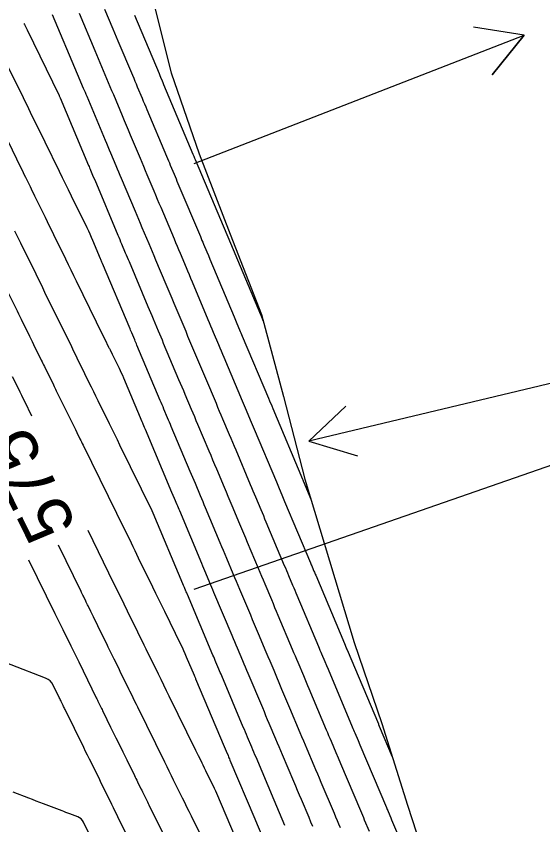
# Model space of a CAD drawing. Extents: x 954385 to 988206, y 1868364 to 1924553.
# Drawn here: x 957986.2 to 958048.1, y 1919141.2 to 1919236.3 of the extents above; entities that cross this region are included whole.
import ezdxf

# ---------------------------------------------------------------- set-up
doc = ezdxf.new("R2010")
doc.units = 0
for name, color, linetype in [('24', 7, 'Continuous'), ('26', 7, 'Continuous'), ('5', 7, 'Continuous'), ('6', 7, 'Continuous'), ('7', 7, 'Continuous')]:
    doc.layers.add(name, color=color, linetype=linetype)

msp = doc.modelspace()

# ---------------------------------------------------------------- linework, layer by layer
at = {"layer": '24'}
msp.add_lwpolyline([(958002.021, 1919239.295), (958004.432, 1919229.588), (958007.744, 1919220.082), (958011.352, 1919210.643), (958015.035, 1919201.221), (958017.626, 1919191.554), (958020.15, 1919181.871), (958023.018, 1919172.266), (958025.931, 1919162.671), (958029.184, 1919153.153), (958032.173, 1919143.575), (958035.293, 1919134.026), (958036.808, 1919124.117), (958038.226, 1919114.187), (958040.213, 1919104.384), (958041.632, 1919094.454), (958042.392, 1919084.376), (958043.229, 1919074.315), (958044.113, 1919064.265)], dxfattribs=at)
at = {"layer": '26'}
for points in [[(958007.131, 1919218.928), (958045.875, 1919234.038), (958042.124, 1919229.355), (958045.875, 1919234.038), (958039.944, 1919234.945)], [(958157.131, 1919218.928), (958020.586, 1919186.323), (958024.943, 1919190.448), (958020.586, 1919186.323), (958026.337, 1919184.612)], [(958007.131, 1919168.928), (958086.983, 1919196.694), (958083.061, 1919192.154), (958086.983, 1919196.694), (958081.09, 1919197.821)]]:
    msp.add_lwpolyline(points, dxfattribs=at)
at = {"layer": '6'}
for points in [[(958000.126, 1919236.367), (958003.015, 1919229.499), (958003.103, 1919229.29), (958003.191, 1919229.08), (958003.368, 1919228.661), (958003.456, 1919228.451), (958003.544, 1919228.242), (958006.998, 1919220.027), (958007.085, 1919219.821), (958007.193, 1919219.564), (958007.258, 1919219.409), (958010.962, 1919210.61), (958011.088, 1919210.312), (958014.918, 1919201.21), (958014.953, 1919201.127), (958015.248, 1919200.428)], [(958024.32, 1919140.894), (958024.142, 1919141.313), (958023.965, 1919141.733), (958023.788, 1919142.152), (958023.61, 1919142.572), (958022.061, 1919146.233), (958021.855, 1919146.719), (958021.65, 1919147.205), (958021.444, 1919147.691), (958021.238, 1919148.177), (958020.416, 1919150.121), (958020.21, 1919150.607), (958020.005, 1919151.093), (958019.8, 1919151.579), (958019.594, 1919152.066), (958018.375, 1919154.959), (958018.143, 1919155.509), (958017.911, 1919156.058), (958017.68, 1919156.608), (958017.448, 1919157.158), (958016.515, 1919159.372), (958016.286, 1919159.914), (958016.058, 1919160.456), (958015.83, 1919160.997), (958015.602, 1919161.539), (958014.689, 1919163.706), (958014.461, 1919164.247), (958014.233, 1919164.789), (958014.005, 1919165.331), (958013.777, 1919165.872), (958012.498, 1919168.907), (958012.306, 1919169.363), (958012.114, 1919169.819), (958011.922, 1919170.275), (958011.73, 1919170.731), (958010.964, 1919172.555), (958010.773, 1919173.011), (958010.581, 1919173.467), (958010.39, 1919173.923), (958010.198, 1919174.379), (958008.482, 1919178.47), (958008.331, 1919178.828), (958008.181, 1919179.186), (958008.03, 1919179.543), (958007.88, 1919179.901), (958007.276, 1919181.332), (958007.126, 1919181.69), (958006.975, 1919182.048), (958006.824, 1919182.406), (958006.673, 1919182.763), (958004.452, 1919188.036), (958004.344, 1919188.292), (958004.236, 1919188.549), (958004.127, 1919188.805), (958004.019, 1919189.062), (958003.587, 1919190.088), (958003.479, 1919190.344), (958003.371, 1919190.601), (958003.263, 1919190.857), (958003.154, 1919191.114), (958000.422, 1919197.591), (958000.355, 1919197.751), (958000.287, 1919197.911), (958000.22, 1919198.071), (958000.152, 1919198.232), (957999.815, 1919199.033), (957999.68, 1919199.353), (957999.613, 1919199.513), (957996.385, 1919207.184), (957996.308, 1919207.368), (957996.191, 1919207.645), (957996.152, 1919207.738), (957995.245, 1919209.894), (957995.085, 1919210.267), (957994.919, 1919210.638), (957994.749, 1919211.007), (957994.572, 1919211.373), (957992.737, 1919215.12), (957992.385, 1919215.838), (957992.033, 1919216.556), (957991.681, 1919217.275), (957991.329, 1919217.993), (957989.645, 1919221.432), (957989.431, 1919221.867), (957989.217, 1919222.303), (957989.004, 1919222.739), (957988.79, 1919223.175), (957987.936, 1919224.918), (957987.723, 1919225.354), (957987.509, 1919225.79), (957987.296, 1919226.226), (957987.082, 1919226.662), (957984.684, 1919231.558)], [(958008.14, 1919139.572), (958006.808, 1919142.274), (958006.547, 1919142.802), (958006.287, 1919143.329), (958006.027, 1919143.856), (958005.767, 1919144.384), (958004.727, 1919146.493), (958004.467, 1919147.02), (958004.207, 1919147.548), (958003.948, 1919148.076), (958003.688, 1919148.603), (958000.521, 1919155.056), (958000.352, 1919155.401), (958000.183, 1919155.745), (957999.76, 1919156.607), (957999.591, 1919156.951), (957999.507, 1919157.124), (957998.448, 1919159.28), (957998.273, 1919159.638), (957998.097, 1919159.995), (957997.922, 1919160.352), (957997.746, 1919160.71), (957997.044, 1919162.139), (957996.869, 1919162.496), (957996.693, 1919162.853), (957996.518, 1919163.211), (957996.343, 1919163.568), (957995.297, 1919165.702), (957995.221, 1919165.857), (957995.146, 1919166.012), (957995.07, 1919166.167), (957994.994, 1919166.322), (957994.678, 1919166.97), (957994.609, 1919167.111), (957994.54, 1919167.253), (957994.471, 1919167.394), (957994.401, 1919167.535), (957994.125, 1919168.1), (957994.056, 1919168.241), (957993.987, 1919168.383), (957993.918, 1919168.524), (957993.849, 1919168.665), (957991.192, 1919174.099)]]:
    msp.add_lwpolyline(points, dxfattribs=at)
at = {"layer": '7'}
for points in [[(957993.622, 1919236.596), (957995.457, 1919232.234), (957996.054, 1919230.814), (957996.85, 1919228.922), (957997.049, 1919228.449), (957997.248, 1919227.976), (957997.447, 1919227.502), (957997.646, 1919227.029), (957998.679, 1919224.577), (957998.917, 1919224.01), (957999.155, 1919223.444), (957999.393, 1919222.878), (957999.632, 1919222.311), (958000.783, 1919219.572), (958000.986, 1919219.091), (958001.188, 1919218.611), (958001.39, 1919218.13), (958001.592, 1919217.649), (958002.401, 1919215.727), (958002.603, 1919215.246), (958002.805, 1919214.766), (958003.008, 1919214.285), (958003.21, 1919213.804), (958004.776, 1919210.085), (958004.952, 1919209.666), (958005.128, 1919209.247), (958005.305, 1919208.828), (958005.481, 1919208.409), (958006.186, 1919206.732), (958006.363, 1919206.313), (958006.539, 1919205.894), (958006.715, 1919205.475), (958006.892, 1919205.056), (958008.758, 1919200.622), (958008.913, 1919200.252), (958009.069, 1919199.882), (958009.225, 1919199.512), (958009.381, 1919199.143), (958010.005, 1919197.664), (958010.161, 1919197.294), (958010.316, 1919196.925), (958010.472, 1919196.555), (958010.628, 1919196.185), (958012.78, 1919191.079), (958012.898, 1919190.799), (958013.016, 1919190.519), (958013.134, 1919190.24), (958013.252, 1919189.96), (958013.723, 1919188.841), (958013.841, 1919188.561), (958013.959, 1919188.281), (958014.077, 1919188.002), (958014.195, 1919187.722), (958016.802, 1919181.536), (958016.882, 1919181.346), (958016.962, 1919181.156), (958017.042, 1919180.965), (958017.122, 1919180.775), (958017.442, 1919180.014), (958017.522, 1919179.823), (958017.602, 1919179.633), (958017.682, 1919179.442), (958017.762, 1919179.252), (958020.793, 1919172.035), (958020.844, 1919171.912), (958020.896, 1919171.79), (958020.947, 1919171.667), (958020.999, 1919171.545), (958021.205, 1919171.056), (958021.257, 1919170.933), (958021.308, 1919170.811), (958021.36, 1919170.688), (958021.411, 1919170.566), (958024.788, 1919162.548), (958024.865, 1919162.365), (958025.044, 1919161.94), (958025.095, 1919161.818), (958028.768, 1919153.106), (958028.795, 1919153.043), (958028.875, 1919152.853), (958030.408, 1919149.229)], [(957996.626, 1919237.071), (957997.6, 1919234.755), (957998.184, 1919233.366), (957999.893, 1919229.304), (958000.034, 1919228.968), (958000.176, 1919228.633), (958000.317, 1919228.297), (958000.458, 1919227.961), (958001.023, 1919226.619), (958001.164, 1919226.283), (958001.305, 1919225.948), (958001.447, 1919225.612), (958001.588, 1919225.276), (958003.891, 1919219.8), (958004.003, 1919219.534), (958004.115, 1919219.268), (958004.227, 1919219.002), (958004.338, 1919218.735), (958004.786, 1919217.671), (958004.898, 1919217.405), (958005.01, 1919217.139), (958005.122, 1919216.873), (958005.234, 1919216.607), (958007.869, 1919210.347), (958007.962, 1919210.125), (958008.056, 1919209.903), (958008.149, 1919209.681), (958008.243, 1919209.46), (958008.616, 1919208.572), (958008.803, 1919208.128), (958008.99, 1919207.684), (958011.838, 1919200.916), (958011.917, 1919200.727), (958011.996, 1919200.539), (958012.076, 1919200.351), (958012.155, 1919200.163), (958012.473, 1919199.409), (958012.552, 1919199.221), (958012.632, 1919199.033), (958012.711, 1919198.845), (958012.79, 1919198.656), (958015.857, 1919191.381), (958015.986, 1919191.074), (958016.244, 1919190.461), (958016.373, 1919190.155), (958019.876, 1919181.844), (958019.903, 1919181.781), (958019.955, 1919181.657), (958020.851, 1919179.523)], [(957990.474, 1919236.463), (957993.417, 1919229.468), (957994.12, 1919227.796), (957994.221, 1919227.557), (957994.321, 1919227.319), (957994.421, 1919227.08), (957994.522, 1919226.841), (957996.691, 1919221.687), (957996.848, 1919221.314), (957997.005, 1919220.94), (957997.162, 1919220.567), (957997.319, 1919220.194), (957997.947, 1919218.701), (957998.104, 1919218.327), (957998.261, 1919217.954), (957998.418, 1919217.581), (957998.575, 1919217.207), (958000.201, 1919213.343), (958000.401, 1919212.867), (958000.601, 1919212.392), (958000.801, 1919211.917), (958001.001, 1919211.442), (958001.801, 1919209.54), (958002.001, 1919209.065), (958002.201, 1919208.59), (958002.401, 1919208.115), (958002.601, 1919207.639), (958003.809, 1919204.769), (958004.042, 1919204.215), (958004.275, 1919203.66), (958004.509, 1919203.106), (958004.742, 1919202.552), (958005.678, 1919200.328), (958005.91, 1919199.776), (958006.142, 1919199.225), (958006.374, 1919198.674), (958006.607, 1919198.123), (958007.536, 1919195.919), (958007.769, 1919195.368), (958008.001, 1919194.817), (958008.234, 1919194.266), (958008.466, 1919193.715), (958009.704, 1919190.777), (958009.897, 1919190.32), (958010.089, 1919189.863), (958010.282, 1919189.405), (958010.475, 1919188.948), (958011.246, 1919187.118), (958011.438, 1919186.661), (958011.631, 1919186.204), (958011.824, 1919185.746), (958012.017, 1919185.289), (958013.728, 1919181.229), (958013.881, 1919180.864), (958014.035, 1919180.499), (958014.189, 1919180.134), (958014.342, 1919179.769), (958014.955, 1919178.308), (958015.108, 1919177.943), (958015.262, 1919177.578), (958015.415, 1919177.212), (958015.568, 1919176.847), (958017.724, 1919171.715), (958017.846, 1919171.424), (958017.968, 1919171.133), (958018.091, 1919170.842), (958018.214, 1919170.55), (958018.704, 1919169.386), (958018.827, 1919169.095), (958018.95, 1919168.804), (958019.072, 1919168.512), (958019.195, 1919168.221), (958021.724, 1919162.217), (958021.818, 1919161.993), (958021.912, 1919161.769), (958022.006, 1919161.545), (958022.101, 1919161.322), (958022.478, 1919160.427), (958022.667, 1919159.979), (958022.855, 1919159.532), (958025.71, 1919152.759), (958025.785, 1919152.583), (958025.859, 1919152.407), (958025.933, 1919152.231), (958026.008, 1919152.055), (958026.38, 1919151.174), (958026.604, 1919150.646), (958029.718, 1919143.287), (958029.769, 1919143.167), (958029.82, 1919143.047), (958029.87, 1919142.926), (958029.921, 1919142.806), (958030.226, 1919142.084), (958030.327, 1919141.844), (958033.156, 1919135.141)], [(957987.139, 1919235.39), (957987.199, 1919235.268), (957987.509, 1919234.635), (957991.237, 1919227.023), (957991.253, 1919226.991), (957991.268, 1919226.959), (957991.282, 1919226.926), (957991.296, 1919226.894), (957991.397, 1919226.653), (957994.735, 1919218.722), (957994.795, 1919218.579), (957994.855, 1919218.437), (957994.915, 1919218.294), (957994.975, 1919218.152), (957995.214, 1919217.582), (957995.334, 1919217.297), (957995.454, 1919217.012), (957998.176, 1919210.54), (957998.286, 1919210.279), (957998.396, 1919210.019), (957998.506, 1919209.758), (957998.615, 1919209.497), (957999.054, 1919208.454), (957999.164, 1919208.194), (957999.274, 1919207.933), (957999.383, 1919207.672), (957999.493, 1919207.412), (958001.711, 1919202.141), (958001.861, 1919201.784), (958002.011, 1919201.427), (958002.162, 1919201.069), (958002.312, 1919200.712), (958002.914, 1919199.283), (958003.064, 1919198.925), (958003.214, 1919198.568), (958003.365, 1919198.211), (958003.516, 1919197.854), (958005.317, 1919193.584), (958005.501, 1919193.147), (958005.686, 1919192.709), (958005.871, 1919192.271), (958006.055, 1919191.833), (958006.793, 1919190.081), (958006.978, 1919189.644), (958007.162, 1919189.206), (958007.347, 1919188.768), (958007.531, 1919188.33), (958008.852, 1919185.197), (958009.077, 1919184.661), (958009.303, 1919184.126), (958009.529, 1919183.59), (958009.754, 1919183.055), (958010.657, 1919180.913), (958010.882, 1919180.378), (958011.108, 1919179.842), (958011.333, 1919179.307), (958011.558, 1919178.771), (958012.468, 1919176.602), (958012.695, 1919176.062), (958012.921, 1919175.522), (958013.148, 1919174.982), (958013.375, 1919174.442), (958014.654, 1919171.396), (958014.848, 1919170.936), (958015.041, 1919170.476), (958015.235, 1919170.016), (958015.429, 1919169.556), (958016.204, 1919167.716), (958016.398, 1919167.256), (958016.591, 1919166.796), (958016.785, 1919166.336), (958016.979, 1919165.876), (958018.659, 1919161.886), (958018.822, 1919161.499), (958018.985, 1919161.112), (958019.148, 1919160.726), (958019.311, 1919160.339), (958019.963, 1919158.792), (958020.126, 1919158.406), (958020.289, 1919158.019), (958020.452, 1919157.632), (958020.615, 1919157.245), (958022.652, 1919152.412), (958022.792, 1919152.081), (958022.932, 1919151.75), (958023.072, 1919151.419), (958023.212, 1919151.088), (958023.772, 1919149.764), (958024.052, 1919149.102), (958024.332, 1919148.44), (958026.664, 1919142.93), (958026.778, 1919142.66), (958026.892, 1919142.39), (958027.006, 1919142.12), (958027.12, 1919141.85), (958027.69, 1919140.5)], [(957983.642, 1919224.841), (957986.787, 1919218.421), (957986.921, 1919218.147), (957987.056, 1919217.873), (957987.19, 1919217.599), (957987.324, 1919217.325), (957987.862, 1919216.229), (957987.996, 1919215.955), (957988.13, 1919215.68), (957988.264, 1919215.406), (957988.399, 1919215.132), (957989.623, 1919212.633), (957989.872, 1919212.125), (957990.121, 1919211.617), (957990.37, 1919211.109), (957990.618, 1919210.601), (957992.02, 1919207.74), (957992.337, 1919207.094), (957992.654, 1919206.447), (957992.97, 1919205.801), (957993.287, 1919205.155), (957996.423, 1919198.753), (957996.649, 1919198.291), (957997.096, 1919197.379), (957997.136, 1919197.296), (957997.177, 1919197.213), (957997.218, 1919197.13), (957997.259, 1919197.047), (957997.503, 1919196.55), (957997.585, 1919196.384), (957998.317, 1919194.893), (957998.451, 1919194.616), (957998.58, 1919194.337), (957998.706, 1919194.057), (957998.828, 1919193.774), (958000.992, 1919188.643), (958001.056, 1919188.493), (958001.119, 1919188.343), (958001.277, 1919187.967), (958001.372, 1919187.742), (958004.495, 1919180.33), (958004.647, 1919179.97), (958004.799, 1919179.61), (958005.102, 1919178.889), (958005.178, 1919178.709), (958005.254, 1919178.529), (958005.33, 1919178.349), (958005.405, 1919178.168), (958008.005, 1919171.974), (958008.123, 1919171.693), (958008.241, 1919171.412), (958008.359, 1919171.131), (958008.477, 1919170.849), (958008.95, 1919169.724), (958009.068, 1919169.443), (958009.186, 1919169.162), (958009.305, 1919168.881), (958009.423, 1919168.6), (958011.56, 1919163.528), (958011.718, 1919163.155), (958011.875, 1919162.782), (958012.032, 1919162.409), (958012.189, 1919162.036), (958012.817, 1919160.545), (958012.974, 1919160.172), (958013.131, 1919159.799), (958013.288, 1919159.426), (958013.445, 1919159.053), (958015.148, 1919155.013), (958015.341, 1919154.556), (958015.534, 1919154.098), (958015.727, 1919153.64), (958015.92, 1919153.182), (958016.691, 1919151.352), (958016.884, 1919150.894), (958017.078, 1919150.436), (958017.271, 1919149.979), (958017.464, 1919149.521), (958018.799, 1919146.366), (958019.023, 1919145.837), (958019.247, 1919145.308), (958019.471, 1919144.779), (958019.695, 1919144.25), (958020.59, 1919142.134), (958020.814, 1919141.605), (958021.038, 1919141.076)], [(958017.794, 1919141.167), (958017.161, 1919142.663), (958016.845, 1919143.412), (958016.528, 1919144.16), (958014.4, 1919149.19), (958014.275, 1919149.485), (958014.15, 1919149.779), (958014.026, 1919150.074), (958013.902, 1919150.369), (958013.405, 1919151.548), (958013.28, 1919151.843), (958013.156, 1919152.137), (958013.032, 1919152.432), (958012.908, 1919152.727), (958010.376, 1919158.734), (958010.29, 1919158.938), (958010.204, 1919159.142), (958010.118, 1919159.346), (958010.032, 1919159.55), (958009.688, 1919160.367), (958009.602, 1919160.571), (958009.516, 1919160.775), (958009.43, 1919160.979), (958009.344, 1919161.183), (958006.348, 1919168.292), (958006.304, 1919168.399), (958006.259, 1919168.505), (958006.214, 1919168.612), (958006.169, 1919168.718), (958005.991, 1919169.144), (958005.901, 1919169.357), (958005.812, 1919169.57), (958002.329, 1919177.867), (958002.256, 1919178.041), (958002.245, 1919178.066), (958002.234, 1919178.09), (958002.223, 1919178.115), (958002.211, 1919178.139), (957998.426, 1919185.852), (957998.118, 1919186.479), (957997.81, 1919187.107), (957997.502, 1919187.734), (957997.193, 1919188.361), (957995.862, 1919191.071), (957995.603, 1919191.598), (957995.344, 1919192.125), (957995.085, 1919192.651), (957994.827, 1919193.178), (957993.792, 1919195.285), (957993.533, 1919195.811), (957993.274, 1919196.338), (957993.016, 1919196.865), (957992.758, 1919197.392), (957989.618, 1919203.801), (957989.358, 1919204.332), (957988.924, 1919205.217), (957988.751, 1919205.571), (957988.578, 1919205.925), (957987.47, 1919208.187), (957987.297, 1919208.539), (957987.125, 1919208.891), (957986.952, 1919209.243), (957986.78, 1919209.595), (957986.09, 1919211.004)], [(957985.305, 1919203.764), (957986.353, 1919201.625), (957986.513, 1919201.296), (957986.674, 1919200.968), (957986.835, 1919200.64), (957986.995, 1919200.312), (957987.638, 1919198.999), (957987.798, 1919198.671), (957987.959, 1919198.343), (957988.12, 1919198.015), (957988.28, 1919197.687), (957989.186, 1919195.84), (957989.278, 1919195.651), (957989.371, 1919195.462), (957989.463, 1919195.273), (957989.556, 1919195.085), (957990.615, 1919192.931), (957990.699, 1919192.76), (957990.782, 1919192.59), (957990.866, 1919192.419), (957990.95, 1919192.249), (957993.004, 1919188.067), (957993.185, 1919187.7), (957993.365, 1919187.333), (957993.726, 1919186.598), (957993.817, 1919186.414), (957993.907, 1919186.231), (957993.997, 1919186.047), (957994.087, 1919185.863), (957998.007, 1919177.876), (957998.222, 1919177.437), (957998.437, 1919176.999), (957998.652, 1919176.561), (957998.866, 1919176.122), (957999.724, 1919174.367), (957999.938, 1919173.929), (958000.152, 1919173.49), (958000.366, 1919173.051), (958000.581, 1919172.613), (958002.25, 1919169.195), (958002.6, 1919168.479), (958002.951, 1919167.763), (958003.301, 1919167.047), (958003.652, 1919166.332), (958005.546, 1919162.472), (958005.722, 1919162.108), (958005.892, 1919161.742), (958006.057, 1919161.373), (958006.216, 1919161.002), (958007.128, 1919158.838), (958007.188, 1919158.697), (958007.277, 1919158.485), (958007.306, 1919158.415), (958010.667, 1919150.441), (958010.778, 1919150.177), (958010.89, 1919149.913), (958011.112, 1919149.386), (958011.168, 1919149.254), (958011.223, 1919149.122), (958011.279, 1919148.991), (958011.335, 1919148.859), (958014.257, 1919141.953), (958014.535, 1919141.296), (958014.999, 1919140.2)], [(957988.075, 1919189.278), (957987.241, 1919190.975), (957987.064, 1919191.336), (957986.886, 1919191.697), (957986.709, 1919192.059), (957986.532, 1919192.42), (957985.822, 1919193.864)], [(958011.985, 1919139.747), (958009.789, 1919144.936), (958009.666, 1919145.222), (958009.538, 1919145.507), (958009.406, 1919145.789), (958009.271, 1919146.07), (958008.527, 1919147.578), (958008.36, 1919147.916), (958008.193, 1919148.255), (958008.151, 1919148.339), (958008.11, 1919148.424), (958008.068, 1919148.508), (958008.026, 1919148.593), (958007.646, 1919149.368), (958007.491, 1919149.683), (958007.337, 1919149.998), (958004.218, 1919156.351), (958003.898, 1919157.003), (958003.578, 1919157.655), (958003.258, 1919158.307), (958002.938, 1919158.959), (958001.511, 1919161.867), (958001.264, 1919162.369), (958001.018, 1919162.871), (958000.771, 1919163.373), (958000.525, 1919163.875), (957999.313, 1919166.346), (957999.18, 1919166.616), (957999.047, 1919166.887), (957998.915, 1919167.158), (957998.782, 1919167.429), (957998.253, 1919168.513), (957998.12, 1919168.784), (957997.988, 1919169.055), (957997.856, 1919169.326), (957997.723, 1919169.597), (957994.686, 1919175.813)], [(957987.7, 1919172.385), (957990.777, 1919166.087), (957991.01, 1919165.612), (957991.242, 1919165.136), (957991.475, 1919164.66), (957991.709, 1919164.185), (957992.642, 1919162.284), (957992.876, 1919161.808), (957993.109, 1919161.333), (957993.342, 1919160.857), (957993.575, 1919160.382), (957995.634, 1919156.181), (957995.702, 1919156.042), (957995.771, 1919155.903), (957995.839, 1919155.764), (957995.907, 1919155.625), (957996.18, 1919155.068), (957996.248, 1919154.929), (957996.317, 1919154.79), (957996.385, 1919154.651), (957996.453, 1919154.512), (957997.325, 1919152.737), (957997.484, 1919152.416), (957997.642, 1919152.094), (957997.8, 1919151.772), (957997.958, 1919151.451), (957998.591, 1919150.164), (957998.749, 1919149.842), (957998.907, 1919149.52), (957999.065, 1919149.199), (957999.223, 1919148.877), (958000.116, 1919147.056), (958000.21, 1919146.864), (958000.304, 1919146.672), (958000.399, 1919146.48), (958000.493, 1919146.288), (958000.891, 1919145.481), (958000.976, 1919145.309), (958001.061, 1919145.137), (958001.145, 1919144.964), (958001.23, 1919144.792), (958001.57, 1919144.103), (958001.655, 1919143.931), (958001.74, 1919143.759), (958001.825, 1919143.586), (958001.91, 1919143.414), (958003.951, 1919139.278)], [(958000.926, 1919136.617), (957998.188, 1919142.175), (957998.009, 1919142.537), (957997.831, 1919142.899), (957997.652, 1919143.262), (957997.474, 1919143.624), (957996.759, 1919145.072), (957996.58, 1919145.434), (957996.402, 1919145.796), (957996.224, 1919146.158), (957996.046, 1919146.521), (957995.064, 1919148.519), (957994.841, 1919148.972), (957994.618, 1919149.426), (957994.395, 1919149.88), (957994.172, 1919150.334), (957991.984, 1919154.793), (957991.927, 1919154.911), (957991.869, 1919155.028), (957991.812, 1919155.145), (957991.754, 1919155.263), (957991.524, 1919155.732), (957991.467, 1919155.849), (957991.409, 1919155.967), (957991.352, 1919156.084), (957991.294, 1919156.201), (957990.571, 1919157.674), (957990.411, 1919157.938), (957990.213, 1919158.158), (957989.976, 1919158.336), (957989.699, 1919158.471), (957981.567, 1919161.599)], [(957995.906, 1919138.01), (957994.153, 1919141.563), (957994.029, 1919141.768), (957993.873, 1919141.94), (957993.688, 1919142.078), (957993.472, 1919142.183), (957992.546, 1919142.535), (957992.315, 1919142.623), (957992.083, 1919142.711), (957991.852, 1919142.799), (957991.621, 1919142.887), (957989.459, 1919143.709), (957989.021, 1919143.876), (957988.584, 1919144.043), (957988.147, 1919144.21), (957987.71, 1919144.378), (957985.871, 1919145.086)]]:
    msp.add_lwpolyline(points, dxfattribs=at)

# ---------------------------------------------------------------- texts
at = {"layer": '5'}
msp.add_text('575', height=6, rotation=116.13651, dxfattribs=at).set_placement((957993.414, 1919176.382))

doc.saveas('drawing.dxf')
